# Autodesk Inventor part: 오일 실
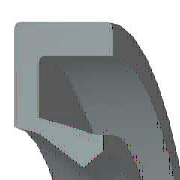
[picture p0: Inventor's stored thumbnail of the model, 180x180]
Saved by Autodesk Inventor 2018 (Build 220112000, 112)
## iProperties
IsCustomPart: 1
Created: 2012-02
Part Number: 오일 실
Material: 고무
Description: 오일 실 - 스프링 장착, 비스프링, 고무 덮개 G
Document SubType Name: Modeling
Standard: JIS B 2402
Designer: mduedu
Standards Organization: JIS
Language: ko-KR
Size Designation: 20 32 5 A
Categories: <MemberInstance><Categories><Category DisplayName="샤프트 부품" InternalName="7f7aeb1f-a693-4053-b835-cee3144e0d98" Mnemonic="SHFT"><Category DisplayName="실링" Intern
Density: 0.93 g/cm^3
Appearance: 고무 - 검은색 - 버전 1.1
Author: mduedu
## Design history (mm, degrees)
body "Solid1"
revolve "회전1" stored, may be unused: angle "d29" = 360 deg
chamfer "모따기1" distance "d30" = 0.25 (= 0.05 x b); stored, may be unused: second distance "d31" = 0.5 (= 0.1 x b), angle "d39" = 45 deg
chamfer "모따기2" distance "d32" = 0.5 (= 0.1 x b); stored, may be unused: second distance "d33" = 0.25 (= 0.05 x b), angle "d40" = 45 deg
fillet "모깎기1" dims "d34" = 0.25 (= 0.05 x b)
sketch "스케치2"
  geometry: L1 (10.997, -3.438)-(11.297, -5); L2 (10.597, -3.282)-(10.997, -3.438); L3 (10, -1.72)-(10.597, -3.282); L4 (11.091, -1.22)-(10, -1.72); L5 (12.133, -3.75)-(11.091, -1.22); L6 (13.333, -3.75)-(12.133, -3.75); L7 (14.667, -1.25)-(13.333, -3.75); L8 (14.667, 0)-(14.667, -1.25); L9 (16, 0)-(14.667, 0); L10 (16, -5)-(16, 0); L11 (11.297, -5)-(16, -5); L12 (0, -9.6)-(0, 1.6) reference; L13 (28, 0)-(14, 0) reference
  constraints: 22 end point, 3 horizontal, 2 vertical
  dimensions: "d2" = 5 distance of L10.start L9.start (= b); "d4" = 1.25 vertical distance of L5.start L1.end (= 0.25 x b); "d6" = 1.33333 distance of L9.start L8.start (= 0.111111 x dd - 0.111111 x Diam); "d8" = 1.25 distance of L8.start L7.start (= 0.25 x b); "d10" = 1.33333 horizontal distance of L7.start L6.start (= 0.111111 x dd - 0.111111 x Diam); "d12" = 1.21951 vertical distance of L9.start L4.start (= 0.243902 x b); "d14" = 1.09091 horizontal distance of L4.start L3.start (= 0.0909091 x dd - 0.0909091 x Diam); "d16" = 0.5 vertical distance of L4.start L3.start (= 0.1 x b); "d18" = 1.2 distance of L6.start L5.start (= 0.1 x dd - 0.1 x Diam); "d20" = 1.5625 vertical distance of L3.start L2.start (= 0.3125 x b); "d22" = 0.59701 horizontal distance of L3.start L2.start (= 0.0497512 x dd - 0.0497512 x Diam); "d24" = 0.3 horizontal distance of L1.start L1.end (= 0.025 x dd - 0.025 x Diam); "d26" = 1.5625 vertical distance of L1.start L1.end (= 0.3125 x b); "d28" = 0.4 horizontal distance of L2.start L1.start (= 0.0333333 x dd - 0.0333333 x Diam); "d35" = 0 distance between parallel lines of L13 L9; "d36" = 16 distance between parallel lines of L12 L10 (= 0.5 x dd); "d37" = 10 distance from line of L12 L3.start (= 0.5 x Diam)
other parameters: "dd" = 32 [user parameter; used in 8 equation terms], "b" = 5 [user parameter; used in 12 equation terms], "d1" = 8 (derived), "d3" = 2 (derived), "d5" = 2.22222 (derived), "d7" = 2 (derived), "d9" = 2.22222 (derived), "d11" = 1.95122 (derived), "d13" = 1.81818 (derived), "d15" = 0.8 (derived), "d17" = 2 (derived), "d19" = 2.5 (derived), "d21" = 0.99502 (derived), "d23" = 0.5 (derived), "d25" = 2.5 (derived), "d27" = 0.66667 (derived), "d38" = 0
